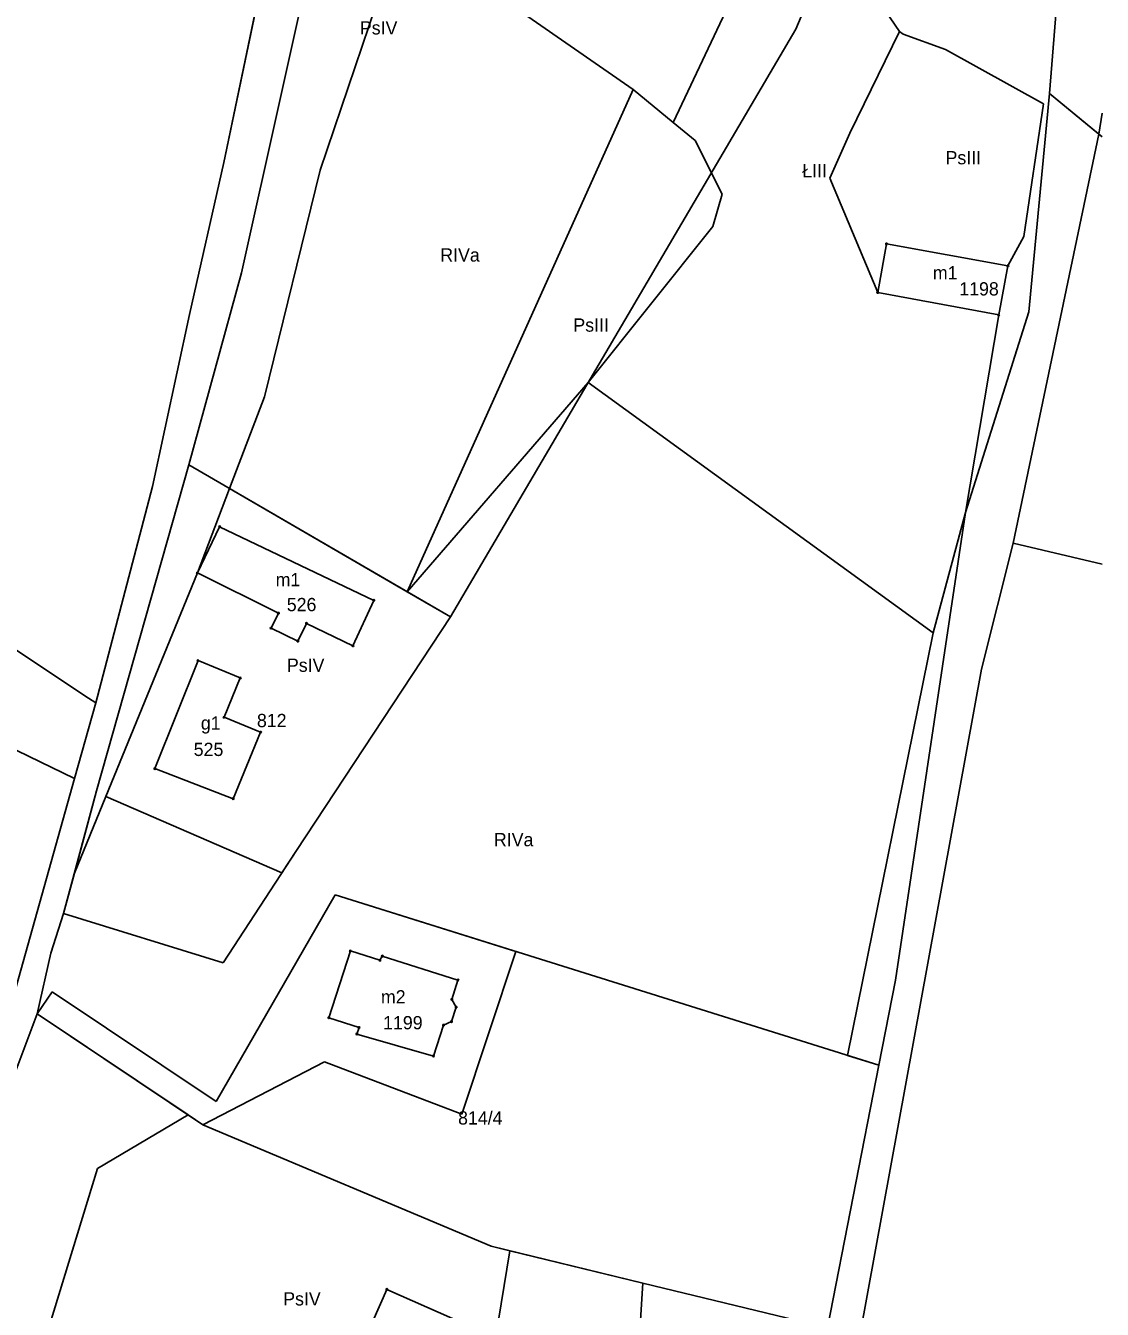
# Model space of a CAD drawing. Extents: x 7498273 to 7499989, y 5499795 to 5500810.
# Drawn here: x 7499867.3 to 7499988.9, y 5500223.1 to 5500368.1 of the extents above; entities that cross this region are included whole.
import ezdxf

# ---------------------------------------------------------------- set-up
doc = ezdxf.new("R2010")
doc.units = 0
for name, color, linetype in [('209-oznaczenie konturu klasyfikacyjnego', 7, 'Continuous'), ('211-numer działki ewidencyjnej', 7, 'Continuous'), ('217-kontur klasyfikacyjny', 7, 'Continuous'), ('218-kontur użytku gruntowego', 7, 'Continuous'), ('219-działka ewidencyjna', 7, 'Continuous'), ('312-budynek ewidencyjny', 7, 'Continuous'), ('312-oznaczenie budynku ewidencyjnego', 7, 'Continuous'), ('312-oznaczenie budynku ewidencyjnego-Atr117', 7, 'Continuous'), ('Punkt budynku', 7, 'Continuous')]:
    doc.layers.add(name, color=color, linetype=linetype)

# ---------------------------------------------------------------- blocks, each defined once
blk = doc.blocks.new('PUNKTBUD')
blk.add_circle((0, 0), 0.09)

msp = doc.modelspace()

# ---------------------------------------------------------------- linework, layer by layer
at = {"layer": '217-kontur klasyfikacyjny'}
for points in [[(7499940.42, 5500357.17), (7499960.84, 5500400.43)], [(7499982.91, 5500360.43), (7499984.72, 5500382.95)], [(7499900.37, 5500379.5), (7499891.63, 5500340.17)], [(7499889.66, 5500352.63), (7499893.92, 5500373.1)], [(7499965.98, 5500367.46), (7499962.1, 5500373.16)], [(7499900.55, 5500351.78), (7499906.84, 5500370.47)], [(7499935.88, 5500360.91), (7499921.16, 5500371.13)], [(7499960.34, 5500355.95), (7499965.98, 5500367.46)], [(7499966.39, 5500367.13), (7499965.98, 5500367.46)], [(7499971.15, 5500365.43), (7499966.39, 5500367.13)], [(7499982.25, 5500359.27), (7499971.15, 5500365.43)], [(7499910.34, 5500304.15), (7499935.88, 5500360.91)], [(7499935.88, 5500360.91), (7499940.42, 5500357.17)], [(7499988.5, 5500355.86), (7499982.91, 5500360.43)], [(7499980.01, 5500344.27), (7499982.25, 5500359.27)], [(7499942.89, 5500355.13), (7499940.42, 5500357.17)], [(7499988.5, 5500355.86), (7499988.876, 5500358.221)], [(7499958.09, 5500350.87), (7499960.34, 5500355.95)], [(7499988.5, 5500355.86), (7499978.82, 5500309.63)], [(7499988.876, 5500355.552), (7499988.5, 5500355.86)], [(7499945.92, 5500349.06), (7499942.89, 5500355.13)], [(7499885.78, 5500335.49), (7499889.66, 5500352.63)], [(7499894.25, 5500326.17), (7499900.55, 5500351.78)], [(7499963.51, 5500337.96), (7499958.09, 5500350.87)], [(7499944.89, 5500345.41), (7499945.92, 5500349.06)], [(7499930.8, 5500327.79), (7499944.89, 5500345.41)], [(7499978.21, 5500340.97), (7499980.01, 5500344.27)], [(7499891.63, 5500340.17), (7499885.71, 5500318.49)], [(7499977.18, 5500335.42), (7499978.21, 5500340.97)], [(7499977.18, 5500335.42), (7499963.51, 5500337.96)], [(7499881.58, 5500316.04), (7499885.78, 5500335.49)], [(7499973.43, 5500313.11), (7499977.18, 5500335.42)], [(7499930.8, 5500327.79), (7499910.34, 5500304.15)], [(7499969.76, 5500299.51), (7499930.8, 5500327.79)], [(7499890.31, 5500315.81), (7499894.25, 5500326.17)], [(7499885.71, 5500318.49), (7499875.27, 5500281.64)], [(7499875.19, 5500291.58), (7499881.58, 5500316.04)], [(7499886.66, 5500306.27), (7499890.31, 5500315.81)], [(7499910.34, 5500304.15), (7499890.31, 5500315.81)], [(7499969.76, 5500299.51), (7499973.43, 5500313.11)], [(7499978.82, 5500309.63), (7499975.23, 5500295.42)], [(7499978.82, 5500309.63), (7499988.876, 5500307.248)], [(7499876.31, 5500281), (7499886.66, 5500306.27)], [(7499910.34, 5500304.15), (7499915.24, 5500301.3)], [(7499915.24, 5500301.3), (7499897.86, 5500274.9)], [(7499960.1, 5500251.77), (7499969.76, 5500299.51)], [(7499872.77, 5500283.05), (7499848.17, 5500294.98)], [(7499975.23, 5500295.42), (7499961.52, 5500220.29)], [(7499872.77, 5500283.05), (7499875.19, 5500291.58)], [(7499865.67, 5500257.64), (7499872.77, 5500283.05)], [(7499875.27, 5500281.64), (7499872.77, 5500272.36)], [(7499876.31, 5500281), (7499872.77, 5500272.36)], [(7499896.21, 5500272.38), (7499876.31, 5500281)], [(7499897.86, 5500274.9), (7499896.21, 5500272.38)], [(7499872.77, 5500272.36), (7499871.54, 5500267.81)], [(7499888.78, 5500246.54), (7499902.23, 5500269.91)], [(7499902.23, 5500269.91), (7499922.64, 5500263.51)], [(7499871.54, 5500267.81), (7499870.11, 5500263.31)], [(7499870.11, 5500263.31), (7499868.56, 5500256.47)], [(7499922.64, 5500263.51), (7499916.53, 5500245.13)], [(7499868.56, 5500256.47), (7499870.26, 5500258.95)], [(7499870.26, 5500258.95), (7499888.78, 5500246.54)], [(7499868.56, 5500256.47), (7499865.98, 5500249.52)], [(7499885.61, 5500245.05), (7499868.56, 5500256.47)], [(7499963.65, 5500250.66), (7499960.1, 5500251.77)], [(7499901.03, 5500251.02), (7499887.29, 5500243.93)], [(7499916.53, 5500245.13), (7499901.03, 5500251.02)], [(7499957.84, 5500220.99), (7499963.65, 5500250.66)], [(7499875.38, 5500238.98), (7499885.61, 5500245.05)], [(7499887.29, 5500243.93), (7499885.61, 5500245.05)], [(7499887.29, 5500243.93), (7499919.83, 5500230.2)], [(7499868.76, 5500217.34), (7499875.38, 5500238.98)], [(7499917.09, 5500199.97), (7499921.96, 5500229.68)], [(7499919.83, 5500230.2), (7499921.96, 5500229.68)], [(7499921.96, 5500229.68), (7499936.97, 5500226.04)], [(7499935.38, 5500200.87), (7499936.97, 5500226.04)], [(7499936.97, 5500226.04), (7499957.84, 5500220.99)]]:
    msp.add_lwpolyline(points, dxfattribs=at)
at = {"layer": '218-kontur użytku gruntowego'}
for points in [[(7499940.42, 5500357.17), (7499960.84, 5500400.43)], [(7499982.91, 5500360.43), (7499984.72, 5500382.95)], [(7499900.37, 5500379.5), (7499891.63, 5500340.17)], [(7499889.66, 5500352.63), (7499893.92, 5500373.1)], [(7499965.98, 5500367.46), (7499962.1, 5500373.16)], [(7499900.55, 5500351.78), (7499906.84, 5500370.47)], [(7499935.88, 5500360.91), (7499921.16, 5500371.13)], [(7499960.34, 5500355.95), (7499965.98, 5500367.46)], [(7499966.39, 5500367.13), (7499965.98, 5500367.46)], [(7499971.15, 5500365.43), (7499966.39, 5500367.13)], [(7499982.25, 5500359.27), (7499971.15, 5500365.43)], [(7499910.34, 5500304.15), (7499935.88, 5500360.91)], [(7499935.88, 5500360.91), (7499940.42, 5500357.17)], [(7499988.5, 5500355.86), (7499982.91, 5500360.43)], [(7499980.01, 5500344.27), (7499982.25, 5500359.27)], [(7499942.89, 5500355.13), (7499940.42, 5500357.17)], [(7499988.5, 5500355.86), (7499988.876, 5500358.221)], [(7499958.09, 5500350.87), (7499960.34, 5500355.95)], [(7499988.5, 5500355.86), (7499978.82, 5500309.63)], [(7499988.876, 5500355.552), (7499988.5, 5500355.86)], [(7499945.92, 5500349.06), (7499942.89, 5500355.13)], [(7499885.78, 5500335.49), (7499889.66, 5500352.63)], [(7499894.25, 5500326.17), (7499900.55, 5500351.78)], [(7499963.51, 5500337.96), (7499958.09, 5500350.87)], [(7499944.89, 5500345.41), (7499945.92, 5500349.06)], [(7499930.8, 5500327.79), (7499944.89, 5500345.41)], [(7499978.21, 5500340.97), (7499980.01, 5500344.27)], [(7499891.63, 5500340.17), (7499885.71, 5500318.49)], [(7499977.18, 5500335.42), (7499978.21, 5500340.97)], [(7499977.18, 5500335.42), (7499963.51, 5500337.96)], [(7499881.58, 5500316.04), (7499885.78, 5500335.49)], [(7499973.43, 5500313.11), (7499977.18, 5500335.42)], [(7499930.8, 5500327.79), (7499910.34, 5500304.15)], [(7499969.76, 5500299.51), (7499930.8, 5500327.79)], [(7499890.31, 5500315.81), (7499894.25, 5500326.17)], [(7499885.71, 5500318.49), (7499875.27, 5500281.64)], [(7499875.19, 5500291.58), (7499881.58, 5500316.04)], [(7499886.66, 5500306.27), (7499890.31, 5500315.81)], [(7499910.34, 5500304.15), (7499890.31, 5500315.81)], [(7499969.76, 5500299.51), (7499973.43, 5500313.11)], [(7499978.82, 5500309.63), (7499975.23, 5500295.42)], [(7499978.82, 5500309.63), (7499988.876, 5500307.248)], [(7499876.31, 5500281), (7499886.66, 5500306.27)], [(7499910.34, 5500304.15), (7499915.24, 5500301.3)], [(7499915.24, 5500301.3), (7499897.86, 5500274.9)], [(7499960.1, 5500251.77), (7499969.76, 5500299.51)], [(7499872.77, 5500283.05), (7499848.17, 5500294.98)], [(7499975.23, 5500295.42), (7499961.52, 5500220.29)], [(7499872.77, 5500283.05), (7499875.19, 5500291.58)], [(7499865.67, 5500257.64), (7499872.77, 5500283.05)], [(7499875.27, 5500281.64), (7499872.77, 5500272.36)], [(7499876.31, 5500281), (7499872.77, 5500272.36)], [(7499896.21, 5500272.38), (7499876.31, 5500281)], [(7499897.86, 5500274.9), (7499896.21, 5500272.38)], [(7499872.77, 5500272.36), (7499871.54, 5500267.81)], [(7499902.23, 5500269.91), (7499888.78, 5500246.54)], [(7499922.64, 5500263.51), (7499902.23, 5500269.91)], [(7499871.54, 5500267.81), (7499870.11, 5500263.31)], [(7499870.11, 5500263.31), (7499868.56, 5500256.47)], [(7499916.53, 5500245.13), (7499922.64, 5500263.51)], [(7499870.26, 5500258.95), (7499868.56, 5500256.47)], [(7499888.78, 5500246.54), (7499870.26, 5500258.95)], [(7499868.56, 5500256.47), (7499865.98, 5500249.52)], [(7499885.61, 5500245.05), (7499868.56, 5500256.47)], [(7499963.65, 5500250.66), (7499960.1, 5500251.77)], [(7499887.29, 5500243.93), (7499901.03, 5500251.02)], [(7499901.03, 5500251.02), (7499916.53, 5500245.13)], [(7499957.84, 5500220.99), (7499963.65, 5500250.66)], [(7499875.38, 5500238.98), (7499885.61, 5500245.05)], [(7499885.61, 5500245.05), (7499887.29, 5500243.93)], [(7499887.29, 5500243.93), (7499919.83, 5500230.2)], [(7499868.76, 5500217.34), (7499875.38, 5500238.98)], [(7499917.09, 5500199.97), (7499921.96, 5500229.68)], [(7499919.83, 5500230.2), (7499921.96, 5500229.68)], [(7499921.96, 5500229.68), (7499936.97, 5500226.04)], [(7499935.38, 5500200.87), (7499936.97, 5500226.04)], [(7499936.97, 5500226.04), (7499957.84, 5500220.99)]]:
    msp.add_lwpolyline(points, dxfattribs=at)
at = {"layer": '219-działka ewidencyjna'}
for points in [[(7499954.25, 5500367.72), (7499973, 5500412.34)], [(7499982.91, 5500360.43), (7499984.72, 5500382.95)], [(7499889.66, 5500352.63), (7499895.13, 5500378.9)], [(7499900.37, 5500379.5), (7499891.63, 5500340.17)], [(7499915.24, 5500301.3), (7499954.25, 5500367.72)], [(7499980.56, 5500335.77), (7499982.91, 5500360.43)], [(7499982.91, 5500360.43), (7499988.876, 5500355.549)], [(7499885.78, 5500335.49), (7499889.66, 5500352.63)], [(7499797.92, 5500342.97), (7499874.37, 5500292.11)], [(7499885.71, 5500318.49), (7499891.63, 5500340.17)], [(7499881.58, 5500316.04), (7499885.78, 5500335.49)], [(7499973.43, 5500313.11), (7499980.56, 5500335.77)], [(7499875.27, 5500281.64), (7499885.71, 5500318.49)], [(7499885.71, 5500318.49), (7499915.24, 5500301.3)], [(7499875.19, 5500291.58), (7499881.58, 5500316.04)], [(7499973.43, 5500313.11), (7499965.52, 5500260.25)], [(7499897.86, 5500274.9), (7499915.24, 5500301.3)], [(7499848.17, 5500294.98), (7499872.77, 5500283.05)], [(7499874.37, 5500292.11), (7499875.19, 5500291.58)], [(7499872.77, 5500283.05), (7499875.19, 5500291.58)], [(7499865.67, 5500257.64), (7499872.77, 5500283.05)], [(7499875.27, 5500281.64), (7499871.54, 5500267.81)], [(7499889.58, 5500262.21), (7499897.86, 5500274.9)], [(7499888.78, 5500246.54), (7499902.23, 5500269.91)], [(7499902.23, 5500269.91), (7499963.65, 5500250.66)], [(7499870.11, 5500263.31), (7499871.54, 5500267.81)], [(7499871.54, 5500267.81), (7499889.58, 5500262.21)], [(7499868.56, 5500256.47), (7499870.11, 5500263.31)], [(7499963.65, 5500250.66), (7499965.52, 5500260.25)], [(7499868.56, 5500256.47), (7499870.26, 5500258.95)], [(7499870.26, 5500258.95), (7499888.78, 5500246.54)], [(7499865.98, 5500249.52), (7499868.56, 5500256.47)], [(7499868.56, 5500256.47), (7499887.29, 5500243.93)], [(7499957.84, 5500220.99), (7499963.65, 5500250.66)], [(7499887.29, 5500243.93), (7499919.83, 5500230.2)], [(7499919.83, 5500230.2), (7499936.97, 5500226.04)], [(7499935.38, 5500200.87), (7499936.97, 5500226.04)], [(7499936.97, 5500226.04), (7499957.84, 5500220.99)]]:
    msp.add_lwpolyline(points, dxfattribs=at)
at = {"layer": '312-budynek ewidencyjny'}
for points in [[(7499963.51, 5500337.96), (7499964.5, 5500343.45)], [(7499964.5, 5500343.45), (7499978.21, 5500340.97)], [(7499978.21, 5500340.97), (7499977.18, 5500335.42)], [(7499977.18, 5500335.42), (7499963.51, 5500337.96)], [(7499886.66, 5500306.27), (7499889.18, 5500311.5)], [(7499889.18, 5500311.5), (7499906.59, 5500303.17)], [(7499895.82, 5500301.73), (7499886.66, 5500306.27)], [(7499906.59, 5500303.17), (7499904.23, 5500298.04)], [(7499894.99, 5500300.03), (7499895.82, 5500301.73)], [(7499898.99, 5500300.58), (7499898.01, 5500298.57)], [(7499904.23, 5500298.04), (7499898.99, 5500300.58)], [(7499898.01, 5500298.57), (7499894.99, 5500300.03)], [(7499881.86, 5500284.16), (7499886.74, 5500296.37)], [(7499886.74, 5500296.37), (7499891.51, 5500294.41)], [(7499891.51, 5500294.41), (7499889.68, 5500289.97)], [(7499889.68, 5500289.97), (7499893.8, 5500288.28)], [(7499893.8, 5500288.28), (7499890.71, 5500280.77)], [(7499890.71, 5500280.77), (7499881.86, 5500284.16)], [(7499901.51, 5500256.02), (7499903.94, 5500263.56)], [(7499903.94, 5500263.56), (7499907.28, 5500262.51)], [(7499907.28, 5500262.51), (7499907.55, 5500262.98)], [(7499907.55, 5500262.98), (7499916.1, 5500260.28)], [(7499916.1, 5500260.28), (7499915.4, 5500258.09)], [(7499915.89, 5500257.21), (7499915.37, 5500255.59)], [(7499915.4, 5500258.09), (7499915.89, 5500257.21)], [(7499904.92, 5500254.92), (7499901.51, 5500256.02)], [(7499915.37, 5500255.59), (7499914.46, 5500255.18)], [(7499904.68, 5500254.18), (7499904.92, 5500254.92)], [(7499913.33, 5500251.69), (7499904.68, 5500254.18)], [(7499914.46, 5500255.18), (7499913.33, 5500251.69)], [(7499906.47, 5500221.73), (7499908.06, 5500225.32)], [(7499908.06, 5500225.32), (7499915.49, 5500222.03)]]:
    msp.add_lwpolyline(points, dxfattribs=at)

# ---------------------------------------------------------------- block references
at = {"layer": 'Punkt budynku'}
for p in [(7499964.5, 5500343.45), (7499978.21, 5500340.97), (7499963.51, 5500337.96), (7499977.18, 5500335.42), (7499889.18, 5500311.5), (7499886.66, 5500306.27), (7499906.59, 5500303.17), (7499895.82, 5500301.73), (7499898.99, 5500300.58), (7499894.99, 5500300.03), (7499898.01, 5500298.57), (7499904.23, 5500298.04), (7499886.74, 5500296.37), (7499891.51, 5500294.41), (7499889.68, 5500289.97), (7499893.8, 5500288.28), (7499881.86, 5500284.16), (7499890.71, 5500280.77), (7499903.94, 5500263.56), (7499907.55, 5500262.98), (7499907.28, 5500262.51), (7499916.1, 5500260.28), (7499915.4, 5500258.09), (7499915.89, 5500257.21), (7499901.51, 5500256.02), (7499915.37, 5500255.59), (7499904.68, 5500254.18), (7499904.92, 5500254.92), (7499914.46, 5500255.18), (7499913.33, 5500251.69), (7499908.06, 5500225.32)]:
    msp.add_blockref('PUNKTBUD', p, dxfattribs=at)

# ---------------------------------------------------------------- texts
at = {"layer": '209-oznaczenie konturu klasyfikacyjnego'}
for s, p in [('PsIV', (7499905.02, 5500367.11)), ('PsIII', (7499971.17, 5500352.44)), ('ŁIII', (7499954.99, 5500350.97)), ('RIVa', (7499914.1, 5500341.45)), ('PsIII', (7499929.13, 5500333.53)), ('PsIV', (7499896.78, 5500295.1)), ('RIVa', (7499920.16, 5500275.39)), ('PsIV', (7499896.36, 5500223.51))]:
    msp.add_text(s, height=1.5, dxfattribs=at).set_placement(p)
at = {"layer": '211-numer działki ewidencyjnej'}
for s, p in [('812', (7499893.39, 5500288.85)), ('814/4', (7499916.11, 5500243.95))]:
    msp.add_text(s, height=1.5, dxfattribs=at).set_placement(p)
at = {"layer": '312-oznaczenie budynku ewidencyjnego'}
for s, p in [('1198', (7499972.72, 5500337.62)), ('526', (7499896.76, 5500301.95)), ('525', (7499886.25, 5500285.59)), ('1199', (7499907.64, 5500254.71))]:
    msp.add_text(s, height=1.5, dxfattribs=at).set_placement(p)
at = {"layer": '312-oznaczenie budynku ewidencyjnego-Atr117'}
for s, p in [('m1', (7499969.735, 5500339.44)), ('m1', (7499895.505, 5500304.77)), ('g1', (7499887.059, 5500288.57)), ('m2', (7499907.396, 5500257.63))]:
    msp.add_text(s, height=1.5, dxfattribs=at).set_placement(p)

doc.saveas('drawing.dxf')
